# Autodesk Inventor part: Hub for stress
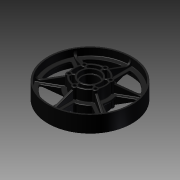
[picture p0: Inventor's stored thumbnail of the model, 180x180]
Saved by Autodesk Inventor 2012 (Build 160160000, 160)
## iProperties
Created: 2011-01
Part Number: Hub for stress
Document SubType Name: Modeling
Designer: Alex
Density: 1.2 g/cm^3
Material: Polycarbonate, Smoke
Author: Alex
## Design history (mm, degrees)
sketch "Sketch1"
  geometry: L1 (0, 63.374)-(0, -54.101); L2 (-65.608, 0)-(-65.608, 12.7); L3 (-65.608, 0)-(-52.908, 0); L4 (-65.608, 12.7)-(-63.182, 12.7); L5 (-63.182, 12.7)-(-63.182, 10.64); L6 (-54.671, 4.669)-(-25.4, 15.265); L7 (-25.4, 15.265)-(-25.4, 18.44); L8 (-25.4, 18.44)-(-22.682, 18.44); L9 (-22.682, 18.44)-(-22.682, 1.587); L10 (-22.682, 1.587)-(-17.005, 1.587); L11 (-17.005, 1.587)-(-17.005, 18.44); L12 (-17.005, 18.44)-(-14.287, 18.44); L13 (-14.287, 18.44)-(-14.287, 12.09); L14 (-14.287, 12.09)-(-12.383, 12.09); L15 (-12.383, 12.09)-(-12.383, 0); L16 (-65.608, 0)-(-12.383, 0); A1 r 6.35 centre (-56.833, 10.64) between (-63.182, 10.64) and (-54.671, 4.669); 2 further points
  constraints: 33 end point, 3 point on line, 2 perpendicular, 2 point on circle, 2 tangent, 1 centre point, 1 collinear, 1 horizontal
  dimensions: "d22" = 12.7 distance of L2.start L2.end; "d24" = 65.6082 distance between parallel lines of L1 L2; "d25" = 63.1825 distance between parallel lines of L5 L1; "d26" = 1.5875 distance from line of L3 point (-63.182, 1.588); "d27" = 3.175 distance from line of L6.end L8; "d30" = 18.4404 distance from line of L8 point (0, 0); "d31" = 2.7178 distance between parallel lines of L9 L7; "d32" = 25.4 distance from line of L7 point (0, 0); "d33" = 14.2875 distance from line of L13 point (0, 0); "d34" = 12.3825 distance from line of point (0, 0) L15; "d35" = 6.35 distance between parallel lines of L14 L12; "d36" = 0 distance from line of L16 point (0, 0); "d37" = 2.7178 distance between parallel lines of L11 L13; "d38" = 6.35 radius of A1; "d99" = 1.5875 distance between parallel lines of L16 L10
revolve "Revolution1" sketch "Sketch1" stored, may be unused: angle "d41" = 90 deg
sketch "Sketch8"
  geometry: L1 (0, 0)-(0, 76.2); L2 (0, 0)-(-65.488, 37.81); L3 (-1.74, 63.159)-(-1.74, 25.34); L4 (-53.827, 33.086)-(-21.075, 14.177); L5 (-55.567, 30.072)-(-22.815, 11.163); L6 (-55.567, -30.072)-(-22.815, -11.163); L7 (-53.827, -33.086)-(-21.075, -14.177); L8 (-1.74, -63.159)-(-1.74, -25.34); L9 (1.74, -63.159)-(1.74, -25.34); L10 (53.827, -33.086)-(21.075, -14.177); L11 (55.567, -30.072)-(22.815, -11.163); L12 (55.567, 30.072)-(22.815, 11.163); L13 (53.827, 33.086)-(21.075, 14.177); L14 (1.74, 63.159)-(1.74, 25.34); C1 r 22.682 at (0, 0) reference; A1 r 63.182 centre (0, 0) between (-1.74, 63.159) and (-53.827, 33.086); A2 r 25.4 centre (0, 0) between (-1.74, 25.34) and (-21.075, 14.177); A3 r 63.182 centre (0, 0) between (-55.567, 30.072) and (-55.567, -30.072); A4 r 25.4 centre (0, 0) between (-22.815, 11.163) and (-22.815, -11.163); A5 r 63.182 centre (0, 0) between (-53.827, -33.086) and (-1.74, -63.159); A6 r 25.4 centre (0, 0) between (-21.075, -14.177) and (-1.74, -25.34); A7 r 63.182 centre (0, 0) between (1.74, -63.159) and (53.827, -33.086); A8 r 25.4 centre (0, 0) between (1.74, -25.34) and (21.075, -14.177); A9 r 63.182 centre (0, 0) between (55.567, -30.072) and (55.567, 30.072); A10 r 25.4 centre (0, 0) between (22.815, -11.163) and (22.815, 11.163); A11 r 63.182 centre (0, 0) between (53.827, 33.086) and (1.74, 63.159); A12 r 25.4 centre (0, 0) between (21.075, 14.177) and (1.74, 25.34)
  constraints: 28 end point, 24 point on circle, 12 centre point, 2 parallel, 1 point on line, 1 vertical, 61 other
  dimensions: "d50" = 60 deg angle of L1 L2; "d51" = 1.7399 distance between parallel lines of L1 L3; "d52" = 1.7399 distance between parallel lines of L4 L2; "d53" = 126.365 diameter of A1; "d54" = 50.8 diameter of A2; "d59" = 360 deg dimension on L2.start L3.start (derived)
extrude "Extrusion3" cut sketch "Sketch8" distance "d61" = 16.8529; taper "d62" = 0 deg
workplane "Work Plane1"
sketch "Sketch10"
  geometry: L1 (-6.35, 54.672)-(-6.35, 32.379); L2 (-44.172, 32.835)-(-24.866, 21.689); L3 (-1.74, 25.34)-(-1.74, 63.159) reference; L4 (-53.827, 33.086)-(-21.075, 14.177) reference; L5 (-50.522, 21.837)-(-31.216, 10.69); L6 (-50.522, -21.837)-(-31.216, -10.69); L7 (-44.172, -32.835)-(-24.866, -21.689); L8 (-6.35, -54.672)-(-6.35, -32.379); L9 (6.35, -54.672)-(6.35, -32.379); L10 (44.172, -32.835)-(24.866, -21.689); L11 (50.522, -21.837)-(31.216, -10.69); L12 (50.522, 21.837)-(31.216, 10.69); L13 (44.172, 32.835)-(24.866, 21.689); L14 (6.35, 54.672)-(6.35, 32.379); A1 r 56.832 centre (0, 0) between (-8.166, 56.243) and (-44.625, 35.193); A2 r 31.75 centre (0, 0) between (-7.56, 30.837) and (-22.926, 21.965); A3 r 31.75 centre (0, 0) between (-6.35, -31.109) and (30.116, -10.055); A4 r 1.588 centre (-7.938, 54.672) between (-6.35, 54.672) and (-8.166, 56.243); A5 r 1.587 centre (-7.937, 32.379) between (-7.56, 30.837) and (-6.35, 32.379); A6 r 1.587 centre (-24.072, 23.063) between (-24.866, 21.689) and (-22.926, 21.965); A7 r 1.588 centre (-43.378, 34.21) between (-44.625, 35.193) and (-44.172, 32.835); A8 r 56.832 centre (0, 0) between (-52.791, 21.05) and (-52.791, -21.05); A9 r 1.588 centre (-51.316, 20.462) between (-50.522, 21.837) and (-52.791, 21.05); A10 r 1.587 centre (-32.01, 9.315) between (-30.485, 8.872) and (-31.216, 10.69); A11 r 31.75 centre (0, 0) between (-30.485, 8.872) and (-30.485, -8.872); A12 r 1.587 centre (-32.01, -9.315) between (-31.216, -10.69) and (-30.485, -8.872); A13 r 1.588 centre (-51.316, -20.462) between (-52.791, -21.05) and (-50.522, -21.837); A14 r 56.832 centre (0, 0) between (-44.625, -35.193) and (-8.166, -56.243); A15 r 1.588 centre (-43.378, -34.21) between (-44.172, -32.835) and (-44.625, -35.193); A16 r 1.587 centre (-24.072, -23.063) between (-22.926, -21.965) and (-24.866, -21.689); A17 r 31.75 centre (0, 0) between (-22.926, -21.965) and (-7.56, -30.837); A18 r 1.587 centre (-7.937, -32.379) between (-6.35, -32.379) and (-7.56, -30.837); A19 r 1.588 centre (-7.938, -54.672) between (-8.166, -56.243) and (-6.35, -54.672); A20 r 56.832 centre (0, 0) between (8.166, -56.243) and (44.625, -35.193); A21 r 1.588 centre (7.938, -54.672) between (6.35, -54.672) and (8.166, -56.243); A22 r 1.587 centre (7.937, -32.379) between (7.56, -30.837) and (6.35, -32.379); A23 r 31.75 centre (0, 0) between (7.56, -30.837) and (22.926, -21.965); A24 r 1.587 centre (24.072, -23.063) between (24.866, -21.689) and (22.926, -21.965); A25 r 1.588 centre (43.378, -34.21) between (44.625, -35.193) and (44.172, -32.835); A26 r 56.832 centre (0, 0) between (52.791, -21.05) and (52.791, 21.05); A27 r 1.588 centre (51.316, -20.462) between (50.522, -21.837) and (52.791, -21.05); A28 r 1.587 centre (32.01, -9.315) between (30.485, -8.872) and (31.216, -10.69); A29 r 31.75 centre (0, 0) between (30.485, -8.872) and (30.485, 8.872); A30 r 1.587 centre (32.01, 9.315) between (31.216, 10.69) and (30.485, 8.872); A31 r 1.588 centre (51.316, 20.462) between (52.791, 21.05) and (50.522, 21.837); A32 r 56.832 centre (0, 0) between (44.625, 35.193) and (8.166, 56.243); A33 r 1.588 centre (43.378, 34.21) between (44.172, 32.835) and (44.625, 35.193); A34 r 1.587 centre (24.072, 23.063) between (22.926, 21.965) and (24.866, 21.689); A35 r 31.75 centre (0, 0) between (22.926, 21.965) and (7.56, 30.837); A36 r 1.587 centre (7.938, 32.379) between (6.35, 32.379) and (7.56, 30.837); A37 r 1.588 centre (7.938, 54.672) between (8.166, 56.243) and (6.35, 54.672); 25 further points
  constraints: 88 point on circle, 37 centre point, 26 point on line, 24 end point, 8 tangent, 2 parallel, 157 other
  dimensions: "d65" = 113.665 diameter of A1; "d66" = 4.6101 distance between parallel lines of L4 L2; "d67" = 4.6101 distance between parallel lines of L3 L1; "d68" = 1.5875 radius of A4; "d69" = 1.5875 radius of A5; "d70" = 1.5875 radius of A6; "d71" = 1.5875 radius of A7; "d74" = 360 deg dimension on point (0, 0) A1.start (derived)
extrude "Extrusion4" cut sketch "Sketch10" stored distance "d76" = 16.764; taper "d77" = 0 deg
sketch "Sketch12"
  geometry: C1 r 22.682 at (0, 0) reference; C2 r 4.267 at (0, 23.812); C3 r 4.267 at (-20.622, 11.906); C4 r 4.267 at (-20.622, -11.906); C5 r 4.267 at (0, -23.812); C6 r 4.267 at (20.622, -11.906); C7 r 4.267 at (20.622, 11.906)
  constraints: 6 centre point, 13 other
  dimensions: "d79" = 8.5344 diameter of C2; "d82" = 360 deg dimension on C1.centre C2.centre (derived); "d97" = 23.8125 distance of C2.centre C1.centre
extrude "Extrusion5" join sketch "Sketch12" distance "d84" = 18.4404; taper "d85" = 0 deg
sketch "Sketch13"
  geometry: A1 r 22.682 centre (0, 23.812) between (17.335, 38.44) and (4, 46.139) reference; 6 further points
  constraints: 7 other
  dimensions: "d88" = 360 deg dimension on A1.centre point (0, 47.625) (derived); "d98" = 23.8125 distance of point (0, 47.625) A1.centre
hole "Hole3" sketch "Sketch13" at (-20.622, 35.719), (0, 47.625), (20.622, 35.719), (20.622, 11.906), (0, 0), (-20.622, 11.906) diameter "d90" = 4.0894; stored, may be unused: countersink angle "d94" = 82 deg, drill point angle "d96" = 118 deg; dims "d91" = 19.05, "d92" = 9.525, "d93" = 6.35, "d95" = 6.35
sketch "Sketch14"
  geometry: L1 (-1.587, 44.45)-(1.587, 44.45); L2 (1.587, 44.45)-(1.587, 39.879); L3 (1.587, 39.879)-(-1.587, 39.879); L4 (-1.587, 39.879)-(-1.587, 44.45); L5 (-14.708, 30.471)-(-18.666, 32.756); L6 (-18.666, 32.756)-(-17.079, 35.506); L7 (-17.079, 35.506)-(-13.12, 33.221); L8 (-13.12, 33.221)-(-14.708, 30.471); L9 (-13.12, 14.404)-(-17.079, 12.119); L10 (-17.079, 12.119)-(-18.666, 14.869); L11 (-18.666, 14.869)-(-14.708, 17.154); L12 (-14.708, 17.154)-(-13.12, 14.404); L13 (1.588, 7.746)-(1.588, 3.175); L14 (1.588, 3.175)-(-1.587, 3.175); L15 (-1.587, 3.175)-(-1.587, 7.746); L16 (-1.587, 7.746)-(1.588, 7.746); L17 (14.708, 17.154)-(18.666, 14.869); L18 (18.666, 14.869)-(17.079, 12.119); L19 (17.079, 12.119)-(13.12, 14.404); L20 (13.12, 14.404)-(14.708, 17.154); L21 (13.12, 33.221)-(17.079, 35.506); L22 (17.079, 35.506)-(18.666, 32.756); L23 (18.666, 32.756)-(14.708, 30.471); L24 (14.708, 30.471)-(13.12, 33.221); A1 r 22.682 centre (0, 23.812) between (17.335, 38.44) and (4, 46.139) reference; A2 r 22.682 centre (0, 23.812) between (21.336, 16.113) and (21.336, 31.512) reference; A3 r 22.682 centre (0, 23.812) between (-17.335, 9.185) and (-4, 1.486) reference; A4 r 22.682 centre (0, 23.812) between (-4, 46.139) and (-17.335, 38.44) reference
  constraints: 48 end point, 2 parallel, 1 horizontal, 1 perpendicular, 49 other
  dimensions: "d100" = 1.5875 distance from line of L4 A3.centre; "d101" = 1.5875 distance from line of L2 A2.centre; "d102" = 20.6375 distance from line of A1.centre L1; "d103" = 16.06653 distance from line of A1.centre L3; "d106" = 360 deg dimension on A4.centre L3.end (derived)
extrude "Extrusion6" join sketch "Sketch14" distance "d108" = 18.4404; taper "d109" = 0 deg
fillet "Fillet1" dims "d110" = 0.79375
fillet "Fillet2" dims "d111" = 0.79375
fillet "Fillet3" dims "d112" = 0.79375
fillet "Fillet4" dims "d113" = 0.79375
fillet "Fillet5" dims "d114" = 0.79375
fillet "Fillet6" dims "d115" = 0.79375
fillet "Fillet7" dims "d116" = 0.79375
fillet "Fillet8" dims "d117" = 0.79375
fillet "Fillet9" dims "d118" = 0.79375
fillet "Fillet10" dims "d119" = 0.79375
fillet "Fillet11" dims "d120" = 0.79375
fillet "Fillet12" dims "d121" = 0.79375
fillet "Fillet13" dims "d122" = 0.79375
fillet "Fillet14" dims "d123" = 0.79375
fillet "Fillet15" dims "d124" = 0.79375
fillet "Fillet16" dims "d125" = 0.79375
fillet "Fillet17" dims "d126" = 0.79375
fillet "Fillet18" dims "d127" = 0.79375
fillet "Fillet19" dims "d128" = 0.79375
fillet "Fillet20" dims "d129" = 0.79375
fillet "Fillet21" dims "d130" = 0.79375
fillet "Fillet22" dims "d131" = 0.79375
fillet "Fillet23" dims "d132" = 0.79375
fillet "Fillet24" dims "d133" = 0.79375
fillet "Fillet25" dims "d134" = 0.79375
fillet "Fillet26" dims "d135" = 0.79375
fillet "Fillet27" dims "d136" = 0.79375
fillet "Fillet28" dims "d137" = 0.79375
fillet "Fillet29" dims "d138" = 0.79375
fillet "Fillet30" dims "d139" = 0.79375
fillet "Fillet31" dims "d140" = 0.79375
fillet "Fillet32" dims "d141" = 0.79375
fillet "Fillet33" dims "d142" = 0.79375
fillet "Fillet34" dims "d143" = 0.79375
fillet "Fillet35" dims "d144" = 0.39687
fillet "Fillet36" dims "d145" = 0.39687
mirror "Mirror1"
body "Solid2"
other parameters: "d42" = 1.7399, "d63" = 12.7, "d64" = 63.5
